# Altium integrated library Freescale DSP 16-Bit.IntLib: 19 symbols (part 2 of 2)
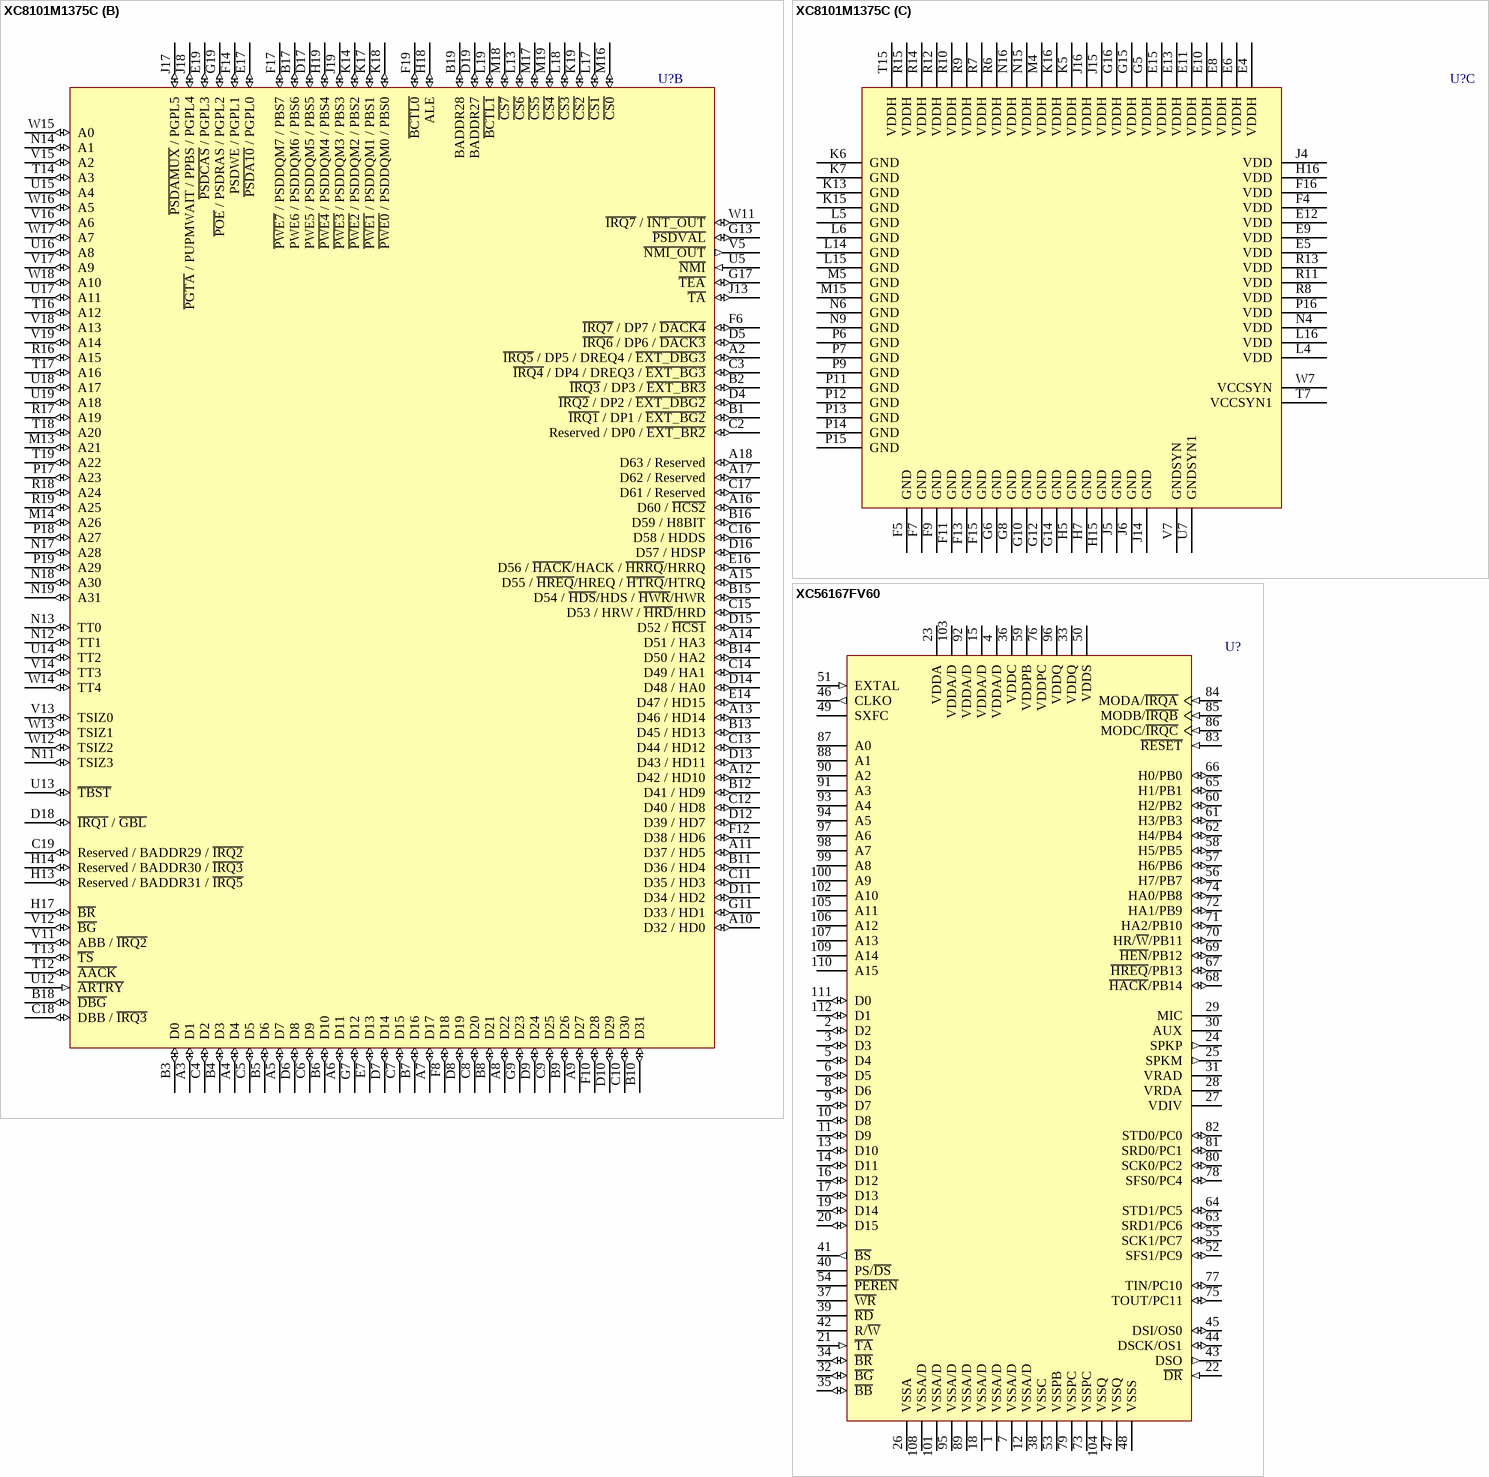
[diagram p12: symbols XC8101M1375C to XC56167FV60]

## XC8101M1375C
designator U?
MSC8100 Family Very High Performance 16-Bit Fixed Point DSP; PinDescriptions: Alternate pin usages may be listed in Pin Description fields.
footprint 1169-01 (BGA, 332-Leads, Body 17x17mm, Pitch 0.8mm)
3D model XC8101-1169-01 (332-Ball FC-P Ball Grid Array 0.8 mm Pitch)
part A pins: C1 THERM1, D1 HPE / EE1 (io), D2 DBREQ / EE0 (io), D3 THERM2, E1 BTM0 / EE4 / EE5 (io), E2 EE3 (io), E3 EE2 (io), E18 ~{MODCK1} / TC0 / BNKSEL0 (io), F1 TDO (out), F2 EED (io), F3 BTM1 / EE5 (io), F18 ~{MODCK2} / TC1 / BNKSEL1 (io), G1 PA31 (io) "/ FCC1:UTOPIA8:TXENB / FCC1:MII:COL", G2 TMS (in), G3 ~{TRST} (in), G4 TCK (io), G18 ~{MODCK3} / TC2 / BNKSEL2 (io), H1 PB30 (io) "/ FCC2:MII:RX_DV / SCC2:TXD / TDBM2:L1RXD", H2 PD31 (io) "/ SCC1:RXD / DRACK1 / DONE1", H3 PC31 (io) "/ BRG1O / CLK1 / TGATE1", H4 PB31 (io) "/ FCC2:MII:TX_ER / SCC2:RXD / TDMB2:L1TXD", H6 TDI (in), J1 PA29 (io) "/ FCC1:UTOPIA8:TXSOC / FCC1:MII:TX_ER", J2 PD30 (io) "/ SCC1:TXD / DMA:DRACK2/DONE2", J3 PC30 (io) "/ EXT1 / BRG2O / CLK2 / TOUT1", J7 PA30 (io) "/ FCC1:UTOPIA8:TXCLAV / FCC1:UTOPIA8:TXCLAV0 / FCC1:MII:CRS / FCC1:HDLC and transparent:RTS", K1 PA28 (io) "/ FCC1:UTOPIA8:RXENB / FCC1:MII:TX_EN", K2 PD29 (io) "/ FCC1:UTOPIA8:RXADDR3 / FCC1:UTOPIA8:RXCLAV2 / SCC1:RTS/TENA", K3 PC29 (io) "/ SCC1:CTS / SCC1:CLSN / BRG3O / CLK3 / TIN2", K4 PB29 (io) "/ FCC2:MII:TX_EN / TDMB2:L1RSYNC", L1 PA27 (io) "/ FCC1:UTOPIA8:RXSOC / FCC1:MII:RX_DV", L2 PB28 (io) "/ FCC2:RX_ER / FCC2:HDLC:RTS / SCC2:RTS/TENA / TDMB2:L1TSYNC", L3 PC28 (io) "/ SCC2:CTS/CLSN / BRG4O / CLK4 / TIN1/TOUT2", L7 PC27 (io) "/ CLK5 / BRG5O / TGATE2", M1 PB27 (io) "/ FCC2:MII:COL / TDMC2:L1TXD", M2 PC26 (io) "/ TMCLK / BRG6O / CLK6 / TOUT3", M3 PB26 (io) "/ FCC2:MII:CRS / TDMC2:L1RXD", M6 PA26 (io) "/ FCC1:UTOPIA8:RXCLAV / FCC1:UTOPIA8:RXCLAV0 / FCC1:MII:RX_ER", M7 PA16 (io) "/ FCC1:UTOPIA8:RXD6 / FCC1:MII and HDLC nibble:RXD1", N1 PC25 (io) "/ DMA:DACK2 / BRG7O / CLK7 / TIN4", N2 PA25 (io) "/ FCC1:UTOPIA8:TXD0 / SDMA:MSNUM0", N3 PB25 (io) "/ FCC2:MII and HDLC nibble:TXD3 / TDMA1:nibble:L1TXD3 / TDMC2:L1TSYNC/GRANT", N5 PC23 (io) "/ EXT2 / DMA:DACK1 / CLK9", N7 PD17 (io) "/ FCC1:UTOPIA8:RXPRTY / SPI:SPIMOSI / BRG2O", N8 CLKIN (in), N10 PC6 (io) "/ FCC1:UTOPIA8:RXADDR2 / FCC1:UTOPIA8:RXADDR2/RXCLAV1 / FCC1:CD / SI2:LIST2", P1 PC24 (io) "/ DMA:DREQ2 / BRG8O / CLK8 / TIN3/TOUT4", P2 PA24 (io) "/ FCC1:UTOPIA8:TXD1 / SDMA:MSNUM1", P3 PB24 (io) "/ FCC2:MII and HDLC nibble:TXD3 / TDMA1:nibble:L1RXD3 / TDMC2:L1RSYNC", P4 PA23 (io) "/ FCC1:UTOPIA8:TXD2", P5 PB20 (io) "/ FCC2:MII and HDLC nibble:RXD1 / TDMA1:nibble:L1TXD1 / TDMD2:L1RSYNC", P8 DLLIN (in), P10 PC4 (io) "/ FCC2:CD / SMC1:SMRXD / SI2:LIST4", R1 PC22 (io) "/ SI1:LIST1 / DREQ1 / CLK10", R2 SPARE1, R3 PA22 (io) "/ FCC1:UTOPIA8:TXD3", R4 PB18 (io) "/ FCC2:MII and HDLC nibble:RXD3 / I2C:SCL", R5 PA19 (io) "/ FCC1:UTOPIA8:TXD6 / FCC1:MII and HDLC nibble:TXD1", T1 PB21 (io) "/ FCC2:MII and HDLC nibble:RXD0 / FCC2:transparent and HDLC serial:RXD /TDMA1:nibble:L1TXD2 / TDMD2:L1TSYNC/GRANT", T2 PB22 (io) "/ FCC2:MII and HDLC nibble TXD0 / FCC2:transparent and HDLC serial TXD /TDMA1:nibble L1RXD1 / TDMD2:L1RXD", T3 PA20 (io) "/ FCC1:UTOPIA8 TXD5 / FCC1:MII and HDLC nibble TXD2", T4 PA17 (io) "/ FCC1:UTOPIA8 RXD7 / FCC1:MII and HDLC nibble RXD0 / FCC1:transparent and HDLC serial RXD", T5 PC13 (io) "/ FCC1:UTOPIA8:TXADDR1 / SCC2:CTS/CLSN / SI1:LIST4", T6 PC14 (io) "/ FCC1:UTOPIA8:RXADDR0 / SCC1:CD/RENA / SI1:LIST2", T8 CLKOUT (out), T9 PA12 (io) "/ FCC1:UTOPIA8:RXD2 / SDMA:MSNUM3", t10 PC7 (io) "/ FCC1:UTOPIA8:TXADDR2 / FCC1:UTOPIA8:TXADDR2/TXCLAV1 / FCC1:CTS / SI1:LIST1", T11 PA6 (io) "/ TDMA1:L2RSYNC", U1 PA21 (io) "/ FCC1:TXD4 / FCC1:MII and HDLC nibble TXD3", U2 PB19 (io) "/ FCC2:MII and HDLC nibble RXD2 / I2C:SDA", U3 PD18 (io) "/ FCC1:UTOPIA8:RXADDR4 / FCC1:UTOPIA8:RXCLAV3 / SPI:SPICLK", U4 PD16 (io) "/ FCC1:UTOPIA8:TXPRTY / SPI:SPIMISO", U6 ~{RSTCONF} (in), U8 PA13 (io) "/ FCC1:UTOPIA8:RXD3 / SDMA:MSNUM2", U9 PA10 (io) "/ FCC1:UTOPIA8:RXD0 / SDMA:MSNUM5", U10 PA8 (io) "/ SMC2:SMRXD / TDMA1:serial L1RXD / TDMA1:nibble L1RXD0", U11 SPARE5, V1 PB23 (io) "/ FCC2:MII and HDLC nibble:TXD1 / TDMA1:nibble:L1RXD2 / TDMD2:L1TXD", V2 PD19 (io) "/ FCC1:UTOPIA8:TXADDR4 / FCC1:UTOPIA:TXCLAV3 / SPI:SPISEL / BRG1O", V3 PC15 (io) "/ FCC1:UTOPIA8:TXADDR0 / SCC1:CTS/CLSN / SMC2:SMTXD", V4 PC12 (io) "/ FCC1:UTOPIA8:RXADDR1 / SCC2:CD/RENA / SI1:LIST3", V6 ~{HRESET} (in), V8 PA11 (io) "/ FCC1:UTOPIA8:RXD1 / SDMA:MSNUM4", V9 PD7 (io) "/ FCC1:UTOPIA8:TXADDR3 / FCC1:UTOPIA8:TXCLAV2 / SMC1:SMSYN", V10 PA7 (io) "/ SMC2:SMSYN / TDMA1:L1TSYNC/GRANT", W2 PA18 (io) "/ FCC1:UTOPIA8:TXD7 / FCC1:MII and HDLC nibble:TXD0 / FCC1:transparent and HDLC serial:TXD", W3 PA15 (io) "/ FCC1:UTOPIA8:RXD5 / FCC1:MII and HDLC nibble:RXD2", W4 ~{SRESET} (in), W5 ~{PORESET} (in), W6 TEST (in), W8 PA14 (io) "/ FCC1:UTOPIA8 RXD4 / FCC1:MII and HDLC nibble:RXD3", W9 PA9 (io) "/ SMC2:SMTXD / TDMA1:serial:L1TXD /TDMA1:nibble:L1TXD0", W10 PC5 (io) "/ FCC2:CTS / SMC1:SMTXD / SI2:LIST3"
part B pins: A2 ~{IRQ5} / DP5 / DREQ4 / ~{EXT_DBG3} (io), A3 D1 (io), A4 D4 (io), A5 D7 (io), A6 D11 (io), A7 D17 (io), A8 D22 (io), A9 D27 (io), A10 D32 / HD0 (io), A11 D37 / HD5 (io), A12 D42 / HD10 (io), A13 D46 / HD14 (io), A14 D51 / HA3 (io), A15 D55 / ~{HREQ}/HREQ / ~{HTRQ}/HTRQ (io), A16 D60 / ~{HCS2} (io), A17 D62 / Reserved (io), A18 D63 / Reserved (io), B1 ~{IRQ1} / DP1 / ~{EXT_BG2} (io), B2 ~{IRQ3} / DP3 / ~{EXT_BR3} (io), B3 D0 (io), B4 D3 (io), B5 D6 (io), B6 D10 (io), B7 D16 (io), B8 D21 (io), B9 D26 (io), B10 D31 (io), B11 D36 / HD4 (io), B12 D41 / HD9 (io), B13 D45 / HD13 (io), B14 D50 / HA2 (io), B15 D54 / ~{HDS}/HDS / ~{HWR}/HWR (io), B16 D59 / H8BIT (io), B17 PWE6 / PSDDQM6 / PBS6 (io), B18 ~{DBG} (io), B19 BADDR28 (io), C2 Reserved / DP0 / ~{EXT_BR2} (io), C3 ~{IRQ4} / DP4 / DREQ3 / ~{EXT_BG3} (io), C4 D2 (io), C5 D5 (io), C6 D9 (io), C7 D15 (io), C8 D20 (io), C9 D25 (io), C10 D30 (io), C11 D35 / HD3 (io), C12 D40 / HD8 (io), C13 D44 / HD12 (io), C14 D49 / HA1 (io), C15 D53 / HRW / ~{HRD}/HRD (io), C16 D58 / HDDS (io), C17 D61 / Reserved (io), C18 DBB / ~{IRQ3} (io), C19 Reserved / BADDR29 / ~{IRQ2} (io), D4 ~{IRQ2} / DP2 / ~{EXT_DBG2} (io), D5 ~{IRQ6} / DP6 / ~{DACK3} (io), D6 D8 (io), D7 D14 (io), D8 D19 (io), D9 D24 (io), D10 D29 (io), D11 D34 / HD2 (io), D12 D39 / HD7 (io), D13 D43 / HD11 (io), D14 D48 / HA0 (io), D15 D52 / ~{HCS1} (io), D16 D57 / HDSP (io), D17 PWE5 / PSDDQM5 / PBS5 (io), D18 ~{IRQ1} / ~{GBL} (io), D19 BADDR27 (io), E7 D13 (io), E14 D47 / HD15 (io), E16 D56 / ~{HACK}/HACK / ~{HRRQ}/HRRQ (io), E17 ~{PSDA10} / PGPL0 (io), E19 ~{PSDCAS} / PGPL3 (io), F6 ~{IRQ7} / DP7 / ~{DACK4} (io), F8 D18 (io), F10 D28 (io), F12 D38 / HD6 (io), F14 PSDWE / PGPL1 (io), F17 ~{PWE7} / PSDDQM7 / PBS7 (io), F19 ~{BCTL0} (io), G7 D12 (io), G9 D23 (io), G11 D33 / HD1 (io), G13 ~{PSDVAL} (io), G17 ~{TEA} (io), G19 ~{POE} / PSDRAS / PGPL2 (io), H13 Reserved / BADDR31 / ~{IRQ5} (io), H14 Reserved / BADDR30 / ~{IRQ3} (io), H17 ~{BR} (io), H18 ALE (io), H19 ~{PWE4} / PSDDQM4 / PBS4 (io), J13 ~{TA} (io), J17 ~{PSDAMUX} / PGPL5 (io), J18 ~{PGTA} / PUPMWAIT / PPBS / PGPL4 (io), J19 ~{PWE3} / PSDDQM3 / PBS3 (io), K14 ~{PWE2} / PSDDQM2 / PBS2 (io), K17 ~{PWE1} / PSDDQM1 / PBS1 (io), K18 ~{PWE0} / PSDDQM0 / PBS0 (io), K19 ~{CS2} (io), L13 ~{CS6} (io), L17 ~{CS1} (io), L18 ~{CS3} (io), L19 ~{BCTL1} (io), M13 A21 (io), M14 A26 (io), M16 ~{CS0} (io), M17 ~{CS5} (io), M18 ~{CS7} (io), M19 ~{CS4} (io), N11 TSIZ3 (io), N12 TT1 (io), N13 TT0 (io), N14 A1 (io), N17 A28 (io), N18 A30 (io), N19 A31 (io), P17 A23 (io), P18 A27 (io), P19 A29 (io), R16 A15 (io), R17 A19 (io), R18 A24 (io), R19 A25 (io), T12 ~{AACK} (io), T13 ~{TS} (io), T14 A3 (io), T16 A12 (io), T17 A16 (io), T18 A20 (io), T19 A22 (io), U5 ~{NMI} (in), U12 ~{ARTRY} (in), U13 ~{TBST} (io), U14 TT2 (io), U15 A4 (io), U16 A8 (io), U17 A11 (io), U18 A17 (io), U19 A18 (io), V5 ~{NMI_OUT} (out), V11 ABB / ~{IRQ2} (io), V12 ~{BG} (io), V13 TSIZ0 (io), V14 TT3 (io), V15 A2 (io), V16 A6 (io), V17 A9 (io), V18 A13 (io), V19 A14 (io), W11 ~{IRQ7} / ~{INT_OUT} (io), W12 TSIZ2 (io), W13 TSIZ1 (io), W14 TT4 (io), W15 A0 (io), W16 A5 (io), W17 A7 (io), W18 A10 (io)
part C pins: E4 VDDH (power), E5 VDD (power), E6 VDDH (power), E8 VDDH (power), E9 VDD (power), E10 VDDH (power), E11 VDDH (power), E12 VDD (power), E13 VDDH (power), E15 VDDH (power), F4 VDD (power), F5 GND (power), F7 GND (power), F9 GND (power), F11 GND (power), F13 GND (power), F15 GND (power), F16 VDD (power), G5 VDDH (power), G6 GND (power), G8 GND (power), G10 GND (power), G12 GND (power), G14 GND (power), G15 VDDH (power), G16 VDDH (power), H5 GND (power), H7 GND (power), H15 GND (power), H16 VDD (power), J4 VDD (power), J5 GND (power), J6 GND (power), J14 GND (power), J15 VDDH (power), J16 VDDH (power), K5 VDDH (power), K6 GND (power), K7 GND (power), K13 GND (power), K15 GND (power), K16 VDDH (power), L4 VDD (power), L5 GND (power), L6 GND (power), L14 GND (power), L15 GND (power), L16 VDD (power), M4 VDDH (power), M5 GND (power), M15 GND (power), N4 VDD (power), N6 GND (power), N9 GND (power), N15 VDDH (power), N16 VDDH (power), P6 GND (power), P7 GND (power), P9 GND (power), P11 GND (power), P12 GND (power), P13 GND (power), P14 GND (power), P15 GND (power), P16 VDD (power), R6 VDDH (power), R7 VDDH (power), R8 VDD (power), R9 VDDH (power), R10 VDDH (power), R11 VDD (power), R12 VDDH (power), R13 VDD (power), R14 VDDH (power), R15 VDDH (power), T7 VCCSYN1 (power), T15 VDDH (power), U7 GNDSYN1 (power), V7 GNDSYN (power), W7 VCCSYN (power)

## XC56167FV60
designator U?
16-Bit Digital Signal Processor
footprint 987-01_N (Thin QFP, 112-Leads, Body 20 x 20mm, Pitch 0.65mm, IPC Medium Density)
footprint 987-01_L (Thin QFP, 112-Leads, Body 20 x 20mm, Pitch 0.65mm, IPC High Density)
footprint 987-01_M (Thin QFP, 112-Leads, Body 20 x 20mm, Pitch 0.65mm, IPC Low Density)
3D model XC56167-987-01 (112-Pin Thin Quad Flat Pack 0.65 mm Pitch)
pins: 1 VSSA/D (power), 2 D2 (io), 3 D3 (io), 4 VDDA/D (power), 5 D4 (io), 6 D5 (io), 7 VSSA/D (power), 8 D6 (io), 9 D7 (io), 10 D8 (io), 11 D9 (io), 12 VSSA/D (power), 13 D10 (io), 14 D11 (io), 15 VDDA/D (power), 16 D12 (io), 17 D13 (io), 18 VSSA/D (power), 19 D14 (io), 20 D15 (io), 21 ~{TA} (in), 22 ~{DR} (in), 23 VDDA (power), 24 SPKP (out), 25 SPKM (out), 26 VSSA (power), 27 VDIV, 28 VRDA (hiz), 29 MIC, 30 AUX, 31 VRAD (hiz), 32 ~{BG} (io), 33 VDDQ (power), 34 ~{BR} (io), 35 ~{BB} (io), 36 VDDC (power), 37 ~{WR} (hiz), 38 VSSC (power), 39 ~{RD} (hiz), 40 PS/~{DS} (hiz), 41 ~{BS} (out), 42 R/~{W} (hiz), 43 DSO (out), 44 DSCK/OS1 (io), 45 DSI/OS0 (io), 46 CLKO (out), 47 VSSQ (power), 48 VSSS (power), 49 SXFC, 50 VDDS (power), 51 EXTAL (in), 52 SFS1/PC9 (io), 53 VSSPB (power), 54 ~{PEREN} (hiz), 55 SCK1/PC7 (io), 56 H7/PB7 (io), 57 H6/PB6 (io), 58 H5/PB5 (io), 59 VDDPB (power), 60 H2/PB2 (io), 61 H3/PB3 (io), 62 H4/PB4 (io), 63 SRD1/PC6 (io), 64 STD1/PC5 (io), 65 H1/PB1 (io), 66 H0/PB0 (io), 67 ~{HREQ}/PB13 (io), 68 ~{HACK}/PB14 (io), 69 ~{HEN}/PB12 (io), 70 HR/~{W}/PB11 (io), 71 HA2/PB10 (io), 72 HA1/PB9 (io), 73 VSSPC (power), 74 HA0/PB8 (io), 75 TOUT/PC11 (io), 76 VDDPC (power), 77 TIN/PC10 (io), 78 SFS0/PC4 (io), 79 VSSPC (power), 80 SCK0/PC2 (io), 81 SRD0/PC1 (io), 82 STD0/PC0 (io), 83 ~{RESET} (in), 84 MODA/~{IRQA} (in), 85 MODB/~{IRQB} (in), 86 MODC/~{IRQC} (in), 87 A0 (hiz), 88 A1 (hiz), 89 VSSA/D (power), 90 A2 (hiz), 91 A3 (hiz), 92 VDDA/D (power), 93 A4 (hiz), 94 A5 (hiz), 95 VSSA/D (power), 96 VDDQ (power), 97 A6 (hiz), 98 A7 (hiz), 99 A8 (hiz), 100 A9 (hiz), 101 VSSA/D (power), 102 A10 (hiz), 103 VDDA/D (power), 104 VSSQ (power), 105 A11 (hiz), 106 A12 (hiz), 107 A13 (hiz), 108 VSSA/D (power), 109 A14 (hiz), 110 A15 (hiz), 111 D0 (io), 112 D1 (io)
